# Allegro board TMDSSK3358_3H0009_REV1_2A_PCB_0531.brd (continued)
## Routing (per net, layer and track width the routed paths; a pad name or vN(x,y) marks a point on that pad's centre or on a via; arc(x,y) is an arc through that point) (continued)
AM335X_MMC0_D3: length 82.7
  TOP w0.14: R3.1 99.82,66.93 99.81,66.95 v1(99.06,66.95) ; U1.3 v1(105.02,63.86)
  LY6_SIG2 w0.127: v1(99.06,66.95) 99.52,67.41 99.52,67.99 99.11,68.4 98.51,68.4 97.92,67.82 94.05,67.82 93.68,67.45 93.68,66.46 93.86,66.27 94.62,66.27 94.8,66.08 94.8,65.82 94.62,65.64 93.86,65.64 93.68,65.45 93.68,65.19 93.86,65 94.62,65 94.8,64.81 94.8,64.55 94.62,64.37 93.86,64.37 93.68,64.18 93.68,63.92 93.86,63.73 94.62,63.73 94.8,63.54 94.8,63.28 94.62,63.1 93.86,63.1 93.68,62.91 93.68,62.65 93.86,62.46 94.62,62.46 94.8,62.27 94.8,62.01 94.62,61.83 93.86,61.83 93.68,61.64 93.68,61.38 93.86,61.19 94.62,61.19 94.8,61 94.8,60.74 94.62,60.56 93.86,60.56 93.68,60.37 93.68,59.38 93.97,59.09 96.88,59.09 97.21,58.76 97.21,55.23 96.94,54.97 92.53,54.97 90.53,56.97 79.45,56.97 77.54,55.05 77.54,53.55 75.67,51.68 75.67,50.2 74.44,48.98 74.44,43.11 75.84,41.72 v2(75.92,41.72)
  BOTTOM w0.14: U26.F17 75.92,39.43 v2(75.92,41.72) ; v1(105.02,63.86) 102.65,63.86 101.2,65.3 100.7,65.3 v1(99.06,66.95) J4.2
AM335X_OSC0_IN: length 14.6
  BOTTOM w0.14: U26.V10 65.86,33.41 65.46,33.02 63.68,33.02 63.25,32.58 63.25,31.87 62.72,31.34 62.72,28.14 62.26,27.69 R216.2 C250.2 60.26,27.3 60.26,27.11 60.11,26.96 58.37,26.96 57.68,27.65 Y6.3
AM335X_OSC0_OUT: length 7.6
  BOTTOM w0.14: R213.1 62.85,32.06 62.85,32.67 63.53,33.35 65.39,33.35 65.86,33.82 67.15,33.82 U26.U11
AM335X_OSC1_IN: length 14.1
  BOTTOM w0.14: U26.A6 82.26,30.21 82.45,30.02 86.52,30.02 87.29,30.79 87.83,30.79 88.19,30.44 88.43,30.44 C247.2 89.13,29.84 89.92,29.06 89.92,27.91 91.36,26.47 Y7.4
AM335X_OSC1_OUT: length 7.9
  BOTTOM w0.14: U26.A4 81.79,28.61 82.45,27.95 86.96,27.95 87.22,27.69 R217.1
AM335X_RGMII1_MDIO_CLK: length 72
  TOP w0.14: R25.2 91.46,46.27 v1(92.84,46.27)
  LY3_SIG1 w0.127: v1(51.05,46.84) 52.54,48.32 53.65,48.32 53.73,48.4 54.8,48.4 55.23,48.83 56.02,48.83 56.53,48.32 60.34,48.32 60.84,47.82 66.1,47.82 67.54,46.37 67.54,42.99 67.62,42.92 67.62,42.87 68.13,42.36 68.13,42.22 68.86,41.49 70.51,41.49 70.75,41.74 70.75,42.65 71.13,43.03 v2(71.13,43.54) 70.78,43.88 70.78,46.01 70.97,46.2 70.97,49.96 73.1,52.08 77.94,52.08 78.16,52.3 87.12,52.3 87.56,51.86 87.56,50.74 88.44,49.86 89.24,49.86 v1(92.84,46.27)
  BOTTOM w0.14: v1(51.05,46.84) R147.2 ; U26.M18 71.54,40.6 71.54,41.95 71.55,41.96 71.55,42.08 71.63,42.16 71.63,43.04 v2(71.13,43.54) ; v1(92.84,46.27) 92.84,44.08 93.81,43.1 U23.1
AM335X_RGMII1_MDIO_DATA: length 79.7
  TOP w0.14: R30.1 91.95,43.48 v1(92.04,43.38)
  LY3_SIG1 w0.127: v1(50.27,46.84) 50.78,46.33 51.41,46.33 52.83,47.75 53.8,47.75 53.94,47.89 55.01,47.89 55.44,48.32 55.81,48.32 56.7,47.43 58.87,47.43 59.11,47.67 60.23,47.67 60.61,47.29 62.95,47.29 66.78,43.47 66.78,41.82 67.41,41.19 70.53,41.19 71.12,41.78 71.12,42.37 v2(71.22,42.47) 71.53,42.16 71.53,41.69 71.78,41.44 72.6,41.44 73.27,42.11 73.27,42.85 74,43.59 75.51,43.59 75.54,43.61 75.85,43.61 76.26,44.02 76.68,44.02 79.57,44.02 79.82,43.76 84.2,43.76 85.12,42.84 85.33,42.84 86.19,41.97 86.19,41.23 86.39,41.04 86.39,40.09 87.01,39.47 87.01,38.96 87.59,38.38 87.96,38.38 87.96,38.38 88.41,38.38 89.33,37.47 89.33,36.71 90.86,35.18 93.17,35.18 94.21,34.14 94.63,34.14 95.27,34.78 95.27,41.12 93.01,43.38 v1(92.04,43.38)
  BOTTOM w0.14: U23.48 93.34,41.95 93.49,42.1 93.49,42.3 92.41,43.38 v1(92.04,43.38) ; U26.M17 71.12,39.43 71.12,42.37 v2(71.22,42.47) ; R148.2 50.04,45.49 50.27,45.72 v1(50.27,46.84)
AM335X_RGMII1_RXCLK: length 43.5
  LY3_SIG1 w0.127: v2(72.45,42.48) 72.3,42.62 72.3,47.25 72.13,47.42 72.13,48.47 73.07,49.42 77.11,49.42 77.38,49.14 79.84,49.14 79.98,49.28 86.54,49.28 88.62,47.19 88.62,46.08 94.19,40.52 94.19,36.38 94.76,35.81 94.76,34.99 v1(94.42,34.65)
  BOTTOM w0.14: R208.2 94.42,33.6 v1(94.42,34.65) ; v2(72.45,42.48) 72.45,42.18 72.68,41.95 72.68,40.57 72.34,40.24 U26.L18
AM335X_RGMII1_RXD0: length 67.9
  LY3_SIG1 w0.127: v1(96.17,55.73) 96.17,43.56 98.36,41.38 98.36,34.36 v1(99.82,32.89)
  LY6_SIG2 w0.127: v2(71.14,38.61) 71.14,41.77 71.62,42.25 71.62,42.63 71.19,43.05 71.02,43.05 70.71,43.37 70.71,44.85 72.02,46.16 73.13,46.16 73.94,46.97 73.94,49.23 75.16,50.45 75.16,51.89 77.03,53.76 77.03,55.3 79.34,57.6 90.73,57.6 91.56,58.44 93.46,58.44 v1(96.17,55.73)
  BOTTOM w0.14: v1(99.82,32.89) 99.31,32.39 R204.2 ; U26.M16 v2(71.14,38.61)
AM335X_RGMII1_RXD1: length 39.7
  LY3_SIG1 w0.127: v1(100.69,30.71) 99.81,29.83 99.81,28.55 98.69,27.43 94.99,27.43 93.02,29.4 92.71,29.4 90.26,31.85 89.91,31.85 87.81,33.95 87.34,33.95 86.4,34.89 86.4,35.14 85.59,35.95 85.59,36.13 85.33,36.39 85.32,36.39 84.54,37.16 84.54,37.76 83.85,38.45 80.83,38.45 79.79,37.41 77.15,37.41 76.36,36.62 74.06,36.62 73.27,37.41 72.34,37.41 v2(71.94,37.81)
  BOTTOM w0.14: v1(100.69,30.71) 100.33,31.07 R203.2 ; U26.L15 v2(71.94,37.81)
AM335X_RGMII1_RXD2: length 43.9
  TOP w0.14: v1(100.85,31.44) 99.91,32.39 R69.2
  LY3_SIG1 w0.127: v2(71.94,38.61) 71.54,38.22 71.54,37.65 72.58,36.62 73.26,36.62 74.06,35.82 76.44,35.82 77.24,36.62 79.72,36.62 81.32,38.23 83.08,38.23 84.04,37.27 84.04,36.42 85.06,35.39 85.4,35.39 85.89,34.91 85.89,34.68 87.13,33.44 87.39,33.44 87.87,32.96 87.89,32.96 88.15,32.7 88.15,32.68 89.52,31.31 89.85,31.31 92.64,28.51 93.15,28.51 94.74,26.92 98.9,26.92 99.47,27.48 99.51,27.48 100.32,28.29 100.32,29.57 101.23,30.49 101.23,31.06 v1(100.85,31.44)
  BOTTOM w0.14: U26.L16 v2(71.94,38.61)
AM335X_RGMII1_RXD3: length 57.4
  TOP w0.14: R71.2 103.66,32.39 v1(103.69,32.41)
  LY3_SIG1 w0.127: v2(71.95,41.83) 71.76,42.02 71.76,47.02 71.62,47.16 71.62,48.79 73.68,50.84 77.69,50.84 78.32,50.22 87.13,50.22 87.71,49.63 87.71,49.01 90.42,46.31 91.35,46.31 95.12,42.55 96.39,42.55 97.78,41.15 97.78,33.03 98.43,32.38 100.03,32.38 100.27,32.63 103.47,32.63 v1(103.69,32.41)
  BOTTOM w0.14: v2(71.95,41.83) 72.39,41.39 72.39,40.63 71.95,40.19 71.95,39.41 U26.L17
AM335X_RGMII1_RXDV: length 33.4
  LY3_SIG1 w0.127: v1(96.22,32.89) 95.58,33.53 94.1,33.53 92.96,34.67 90.65,34.67 88.82,36.5 88.82,37.18 88.13,37.87 87.38,37.87 86.48,38.77 86.48,39.29 86.08,39.68 85.86,39.9 85.86,40.75 84.13,42.48 81.19,42.48 80.49,43.18 79.51,43.18 79.18,43.51 76.47,43.51 76.06,43.1 75.75,43.1 75.51,42.86 75.51,42.82 75.18,42.5 74.02,42.5 v2(73.83,42.7)
  BOTTOM w0.14: R206.2 96.44,32.85 96.27,32.85 v1(96.22,32.89) ; v2(73.83,42.7) 73.55,42.42 73.55,39.41 U26.J17
AM335X_RGMII1_TXCLK: length 32.8
  LY3_SIG1 w0.127: v1(73.39,48.35) 73.92,48.88 76.92,48.88 77.28,48.52 79.94,48.52 80.2,48.26 83.28,48.26 84.37,47.17 85.67,47.17 89.98,42.86 89.98,42.28 90.54,41.72 91.43,41.72 92.92,40.23 v1(92.92,35.71)
  BOTTOM w0.14: U23.35 94.21,36.22 94.11,36.11 94.06,36.11 94,36.05 93.99,36.05 93.98,36.04 93.25,36.04 v1(92.92,35.71) ; R134.1 73.84,46.24 74.25,46.64 74.25,47.5 v1(73.39,48.35)
AM335X_RGMII1_TXD0: length 28.9
  LY3_SIG1 w0.127: v1(73.41,47.3) 75.1,45.62 75.1,45.47 75.41,45.15 76.37,45.15 76.7,44.82 80.28,44.82 80.83,44.27 84.41,44.27 85.33,43.35 85.54,43.35 86.7,42.18 86.7,41.44 86.93,41.21 86.93,40.28 87.29,39.91 88.05,39.91 90.48,37.47 90.48,37.25 90.8,36.92 90.8,35.98 91.1,35.69 92.1,35.69 v1(92.18,35.76)
  BOTTOM w0.14: R135.1 73.41,46.81 v1(73.41,47.3) ; v1(92.18,35.76) 92.66,36.25 92.66,36.57 92.77,36.68 U23.36
AM335X_RGMII1_TXD1: length 21.9
  LY3_SIG1 w0.127: v1(79.84,46.95) 80.34,46.45 80.95,46.45 81.24,46.15 84.71,46.15 88.51,42.35 88.52,42.35 88.96,41.91 88.96,41.73 91.5,39.19 91.5,37.67 91.83,37.33 91.83,36.69 v1(92.08,36.45)
  BOTTOM w0.14: v1(92.08,36.45) 91.83,36.69 91.83,37.11 92.27,37.55 U23.37 ; R130.1 79.01,46.95 v1(79.84,46.95)
AM335X_RGMII1_TXD2: length 27.8
  LY3_SIG1 w0.127: v1(72.76,47.5) 72.76,47.52 73.07,47.83 75.62,47.83 76.45,47 79.11,47 79.51,47.4 80.72,47.4 81.45,46.66 84.92,46.66 88.72,42.86 88.73,42.86 89.47,42.12 89.47,42.07 91.09,40.45 91.75,40.45 92.01,40.19 92.01,37.96 v1(92.01,37.95)
  BOTTOM w0.14: v1(72.76,47.5) 72.4,47.15 72.4,46.82 R136.1 ; v1(92.01,37.95) U23.38
AM335X_RGMII1_TXD3: length 25.9
  LY3_SIG1 w0.127: v1(75.6,45.68) 75.68,45.76 80.79,45.76 81.77,44.78 84.62,44.78 85.54,43.86 85.75,43.86 87.21,42.39 87.21,41.65 90.99,37.87 90.99,37.46 91.31,37.13 v1(91.31,36.2)
  BOTTOM w0.14: R133.1 75.05,46.23 v1(75.6,45.68) ; U23.39 92.28,38.35 92.21,38.42 92.13,38.42 92.13,38.43 91.52,38.43 91,37.91 91,36.76 91.31,36.45 v1(91.31,36.2)
AM335X_RGMII1_TXEN: length 26.5
  LY3_SIG1 w0.127: v1(94.25,35.6) 93.43,36.42 93.43,40.44 91.64,42.23 90.75,42.23 90.49,42.49 90.49,43.07 84.79,48.77 v1(80.67,48.77)
  BOTTOM w0.14: v1(80.67,48.77) 80.4,48.49 80.4,46.67 79.95,46.23 R129.1 ; U23.34 94.61,35.95 94.25,35.59 94.25,35.6 v1(94.25,35.6)
AM335X_RGMII2_RXCLK: length 22.7
  LY3_SIG1 w0.127: v2(67.94,37.81) 66.92,36.79 66.92,35.17 64.26,32.52 64.26,32.34 63.9,31.97 60.51,31.97 60.09,32.4 57.99,32.4 57.58,31.98 57.58,31.59 57.08,31.09 52.98,31.09 52.19,31.88 v1(51.31,31.88)
  BOTTOM w0.14: v1(51.31,31.88) 51.31,31.88 R200.2 ; U26.T15 v2(67.94,37.81)
AM335X_RGMII2_RXD0: length 17.1
  LY3_SIG1 w0.127: v1(56.11,31.85) 56.11,32.2 57.5,33.6 62.93,33.6 64.36,35.03 65,35.03 65.23,35.26 65.23,35.58 64.81,36 64.81,38.25 v2(65.39,38.82)
  BOTTOM w0.14: v1(56.11,31.85) 56.11,32.3 R195.2 ; U26.V17 66.51,39.01 66.5,39.01 66.17,39.01 66.17,39.01 65.57,39.01 v2(65.39,38.82)
AM335X_RGMII2_RXD1: length 17.8
  LY3_SIG1 w0.127: v1(58.42,31.84) 58.42,31.52 58.73,31.21 63.56,31.21 63.76,31.01 64.29,31.01 64.52,31.24 64.52,32.29 67.27,35.04 67.27,36.14 68.33,37.21 68.33,38.22 v2(67.94,38.61)
  BOTTOM w0.14: v1(58.42,31.84) 58.04,31.84 57.8,32.08 57.8,32.3 R194.2 ; U26.T16 v2(67.94,38.61)
AM335X_RGMII2_RXD2: length 16.7
  TOP w0.14: v1(56.81,31.9) 56.81,32.18 R65.2
  LY3_SIG1 w0.127: v2(67.14,38.61) 66.54,38.01 66.54,35.42 64.26,33.15 63.96,33.15 63.5,32.69 61.38,32.69 60.91,33.16 57.68,33.16 56.81,32.3 v1(56.81,31.9)
  BOTTOM w0.14: U26.U16 v2(67.14,38.61)
AM335X_RGMII2_RXD3: length 10.5
  TOP w0.14: R67.2 61.18,33.11 v1(61.72,33.11)
  LY3_SIG1 w0.127: v1(61.72,33.11) 63.35,33.11 63.86,33.63 64.42,33.63 65.72,34.92 65.72,37.99 v2(66.34,38.61)
  BOTTOM w0.14: U26.V16 v2(66.34,38.61)
AM335X_RGMII2_RXDV: length 15.5
  LY3_SIG1 w0.127: v2(63.75,36.61) 63.41,36.27 63.41,35.66 62.37,34.62 62.12,34.62 61.54,34.03 56.9,34.03 v1(54.74,31.88)
  BOTTOM w0.14: v1(54.74,31.88) 54.45,32.17 54.41,32.2 R197.2 ; v2(63.75,36.61) 64.43,36.61 64.73,36.32 66.41,36.32 66.49,36.4 66.53,36.4 U26.V14
AM335X_RGMII2_TXCLK: length 22.9
  LY3_SIG1 w0.127: v1(52.83,34.92) 51.01,34.92 50.02,35.92 50.02,37.85 50.65,38.48 53.53,38.48 53.97,38.04 57.24,38.04 57.46,38.25 60.05,38.25 60.29,38.02 61,38.02 v1(62.65,39.67)
  BOTTOM w0.14: v1(52.83,34.92) 53.27,35.36 53.27,35.57 53.83,36.13 U24.35 ; v1(62.65,39.67) 62,40.32 62,40.54 R168.1
AM335X_RGMII2_TXD0: length 17.8
  LY3_SIG1 w0.127: v1(62.69,38.92) 62.51,38.92 61.18,37.59 60.11,37.59 59.87,37.82 57.64,37.82 57.42,37.6 53.66,37.6 53.56,37.7 51.73,37.7 51.01,36.99 51.01,36.36 51.46,35.92 v1(52.72,35.92)
  BOTTOM w0.14: R174.1 62.1,38.92 v1(62.69,38.92) ; U24.36 53.43,36.2 53.15,35.92 v1(52.72,35.92)
AM335X_RGMII2_TXD1: length 15.6
  TOP w0.14: R51.1 64.4,38.46 64.24,38.61 63.88,38.61 v2(63.63,38.35)
  LY3_SIG1 w0.127: v1(52.09,36.83) 52.79,36.83 52.87,36.74 58.27,36.74 59.19,35.83 61.44,35.83 62.91,37.29 62.91,37.64 v2(63.63,38.35)
  BOTTOM w0.14: U24.37 52.55,37.29 v1(52.09,36.83)
AM335X_RGMII2_TXD2: length 15.1
  LY3_SIG1 w0.127: v1(62.36,37.34) 61.74,37.34 60.66,36.26 59.37,36.26 58.45,37.17 53.26,37.17 53.16,37.27 51.9,37.27 51.46,36.83 v1(51.46,36.54)
  BOTTOM w0.14: R180.1 v1(62.36,37.34) ; U24.38 51.98,37.95 51.46,37.43 v1(51.46,36.54)
AM335X_RGMII2_TXD3: length 19.1
  LY3_SIG1 w0.127: v1(61.8,35.36) 59.04,35.36 58.14,36.26 54.02,36.26 53.23,35.47 51.29,35.47 50.56,36.21 v1(50.56,37.47)
  BOTTOM w0.14: R192.1 61.8,33.93 v1(61.8,35.36) ; U24.39 51.83,38.35 50.94,37.47 v1(50.56,37.47)
AM335X_RGMII2_TXEN: length 14.7
  TOP w0.14: v2(63.63,37.47) 63.91,37.19 64.07,37.19 R56.1
  LY3_SIG1 w0.127: v1(53.91,35.06) 54.21,35.37 56.41,35.37 56.43,35.39 58.4,35.39 58.99,34.8 60.62,34.8 60.73,34.91 62.32,34.91 62.81,35.4 62.81,36.65 v2(63.63,37.47)
  BOTTOM w0.14: U24.34 54.23,36.01 53.91,35.69 v1(53.91,35.06)
AM335X_SPI0_CS0: length 50.2
  TOP w0.14: J11.2 100.72,15.13 v1(100.72,16.58)
  BOTTOM w0.14: U26.A16 80.36,38.23 81.92,38.23 82.39,38.7 83.53,38.7 84.4,37.83 85.54,37.83 R179.1 86.44,36.93 88.12,36.93 91.65,33.4 91.65,32.16 93.14,30.68 94.53,30.68 94.93,31.08 97.93,31.08 99.99,29.02 99.99,28.24 101.21,27.02 104.17,27.02 105.73,25.46 105.73,25.09 104.82,24.18 101.21,24.18 100.34,23.31 100.34,16.96 v1(100.72,16.58)
AM335X_SPI0_CS1: length 40.6
  TOP w0.14: v2(79.14,37.81) 78.74,38.21 78.74,38.78 78.17,39.35 78.17,40.39 78.77,40.98 78.77,41.09 80.15,42.48 84.33,42.48 85.47,43.61 86.96,43.61 88.78,45.43 88.78,45.51 90.9,47.63 95.95,47.63 96.36,47.22 v1(98.36,47.22) ; v1(98.81,57.4) R11.1 98.81,58.3 U2.3
  BOTTOM w0.14: v1(98.36,47.22) 98.04,47.53 98.04,49.92 96.66,51.3 96.66,53.23 98.04,54.62 98.04,55.37 98.8,56.13 J4.10 98.81,56.26 v1(98.81,57.4) ; U26.C15 78.74,37.41 v2(79.14,37.81)
AM335X_SPI0_D0: length 71.4
  BOTTOM w0.14: U26.B17 79.99,39.46 80.48,39.46 81.03,40.01 81.03,40.05 81.8,40.81 83.07,40.81 83.87,40.02 87.92,40.02 88.32,39.62 88.32,38.61 88.25,38.55 88.25,37.32 90.29,35.29 91.36,35.29 92.85,33.8 92.85,31.48 93.29,31.05 94.37,31.05 94.78,31.45 98.08,31.45 100.4,29.13 100.4,28.39 101.4,27.39 104.33,27.39 106.1,25.61 106.1,24.93 104.98,23.81 101.37,23.81 100.72,23.16 100.72,18.24 101.29,17.67 101.29,16.4 100.9,16.01 99,16.01 97.65,14.66 97.2,14.66 96.83,14.3 94.61,14.3 94.22,14.68 93.84,14.68 93.03,15.49 93.03,16.07 92.1,17 92.1,17.46 92.1,18.27 91.76,18.61 91.28,18.61 90.8,18.13 90.44,18.13 90.16,17.85 90.16,16.99 90.11,16.95 90.11,15.47 89.77,15.12 89.77,14.33 J11.6
AM335X_SPI0_D1: length 44.4
  LY6_SIG2 w0.127: v1(84.33,38.61) 84.33,38.58 84.21,38.47 84.21,37.03 84.78,36.46 85.26,36.46 86.29,35.43 86.29,34.87 91.05,30.11 91.05,28.87 92.8,27.11 93.6,27.11 96.8,23.92 96.8,22.77 100.59,18.98 100.59,18.7 v1(101.74,17.55)
  BOTTOM w0.14: v1(101.74,17.55) 101.74,16.33 101.05,15.64 99.15,15.64 97.8,14.3 97.35,14.3 J11.3 ; R177.1 85.63,38.2 84.73,38.2 v1(84.33,38.61) 84.33,38.59 83.8,39.12 82.32,39.12 81.81,38.61 79.93,38.61 U26.B16
AM335X_SPI0_SCLK: length 42.9
  TOP w0.14: J11.5 92.21,14.23 97.64,14.23 98.08,14.23 99.89,16.05 99.89,16.73 101.49,18.33 101.49,21.27 101.49,22.87 101.49,23.18 101.49,27.65 100.65,28.48 100.65,29.87 98.64,31.87 97.83,31.87 97.19,32.51 97.19,33.4 92.19,38.4 90.46,38.4 90.15,38.71 89,38.71 88.29,39.43 87.68,39.43 v1(87.66,39.45)
  BOTTOM w0.14: R171.2 87.61,39.5 v1(87.66,39.45)
AM335X_UART0_CTSN: length 60.3
  LY6_SIG2 w0.127: v1(40.55,29.67) 40.55,31.15 41.89,32.5 43.6,32.5 44.13,31.97 47.02,31.97 47.96,31.03 56.52,31.03 57.63,29.91 63.64,29.91 64.27,30.54 64.27,30.56 64.92,31.21 65.28,31.21 65.6,31.53 65.6,32.44 65.6,32.45 65.6,32.78 65.83,33.01 66.52,33.01 67.7,31.82 68.9,31.82 69.13,32.05 69.13,32.47 70.28,33.62 70.28,36.18 70.71,36.62 72.9,36.62 73.13,36.85 73.13,37.99 72.9,38.22 72.58,38.22 72.34,38.45 72.34,39.5 74.03,41.19 75.95,41.19 76.32,41.56 76.32,42.2 v2(76.79,42.67)
  BOTTOM w0.102: v2(76.79,42.67) 77.14,42.32 U26.E18
  BOTTOM w0.14: U28.40 36.86,28.58 37.93,29.64 40.52,29.64 v1(40.55,29.67)
AM335X_UART0_RTSN: length 199
  TOP w0.14: v1(114.57,29.03) 109.61,33.98 v1(104.47,33.98)
  LY3_SIG1 w0.127: v2(76.75,41.72) 77.67,40.79 80.62,40.79 81.45,39.96 83.19,39.96 83.76,39.38 84.65,39.38 85.26,38.78 85.26,38.32 86.76,36.81 86.76,35.96 87.24,35.49 87.24,35.24 87.69,34.79 88.74,34.79 90.3,33.22 90.85,33.22 95.24,28.83 96.09,28.83 97.23,29.97 98.37,29.97 100.51,32.12 102.99,32.12 103.21,31.9 103.9,31.9 104.26,32.27 104.26,33.07 104.27,33.08 104.27,33.78 104.48,33.98 v1(104.47,33.98) ; v1(33.48,28.78) 29.55,24.84 29.55,23.44 28.39,22.29 28.39,7.7 33.02,3.07 40.78,3.07 40.83,3.12 42.63,3.12 43.97,1.79 55.26,1.79 55.78,2.31 57.96,2.31 59.4,0.88 97.51,0.88 98.03,1.4 110.53,1.4 117.54,8.4 117.54,24.24 114.06,27.72 114.06,28.52 v1(114.57,29.03)
  BOTTOM w0.14: U28.41 33.78,29.08 v1(33.48,28.78) ; U26.E17 76.75,39.41 v2(76.75,41.72) 76.75,42.15 76.35,42.55 76.35,43.42 77.27,44.35 R131.1
AM335X_UART0_RXD: length 72.3
  LY3_SIG1 w0.127: v1(31.13,42.49) 31.13,42.64 32.5,44.01 36.89,44.01 37.15,44.27 37.15,44.51 37.53,44.89 48.34,44.89 50.68,42.56 57.56,42.56 57.99,42.99 59.03,42.99 59.19,42.83 60.28,42.83 61,43.55 61.85,43.55 63.27,42.13 63.72,42.13 66.03,39.81 66.34,39.81 69.82,39.81 70.28,39.35 72.9,39.35 73.14,39.1 73.14,38.45 73.38,38.22 73.69,38.22 73.95,37.96 73.95,37.65 74.18,37.42 76.54,37.42 76.94,37.81 v2(77.54,37.81)
  LY6_SIG2 w0.127: v1(37.19,28.08) 37.19,29.03 34.92,31.3 34.92,35.01 34.3,35.63 34.3,39.44 32.86,40.89 32.73,40.89 v1(31.13,42.49)
  BOTTOM w0.14: U26.E15 v2(77.54,37.81) ; v1(37.19,28.08) 36.69,27.58 U28.38
AM335X_UART0_TXD: length 151
  LY3_SIG1 w0.127: v1(34.88,3.56) 34.27,4.17 33.02,4.17 32.77,4.42 32.77,5.46 29.61,8.62 29.61,21.59 31.61,23.58 31.61,25.4 32.77,26.56 32.91,26.56 33.41,27.06 33.41,27.45 33.11,27.76 v1(33.1,27.76)
  LY6_SIG2 w0.127: v1(34.88,3.56) 42.42,3.56 44.03,5.16 54.74,5.16 56.96,2.95 60.73,2.95 62.47,1.21 83.33,1.21 84.34,2.21 84.5,2.37 87.28,2.37 89.23,4.33 98.87,4.33 100.56,6.01 100.56,11.78 100.15,12.19 100.15,13.71 99.4,14.45 97.87,14.45 94.3,18.02 94.3,20.31 92.79,21.82 92.79,24.63 88.27,29.15 86.38,29.15 84.75,30.77 84.75,31.64 83.56,32.84 82.93,32.84 82.5,33.27 82.22,33.27 81.85,33.64 81.85,34.79 82.26,35.2 82.63,35.2 83.44,36.01 83.44,37.76 82.36,38.84 81.15,38.84 80.98,39.01 77.93,39.01 v2(77.54,38.61)
  BOTTOM w0.14: v1(33.1,27.76) 33.42,28.08 U28.39 ; U26.E16 v2(77.54,38.61)
AM335X_UART1_CTSN: length 82.2
  TOP w0.14: v1(95.81,29.27) 95.81,28.9 98.24,26.47 98.24,25.45 98.82,24.88 98.82,22.24 98.07,21.5 97.36,21.5 97.08,21.78 95.69,21.78 95.61,21.8 95.59,21.8 94.35,21.8 93.82,21.27 93.42,20.87 88.89,20.87 87.67,19.65 81.65,19.65 80.55,18.56 63.94,18.56 63.89,18.61 63.52,18.61 61.07,16.16 58.61,16.16 57.53,17.25 U11.7
  LY3_SIG1 w0.127: v1(95.81,29.27) 95.81,30.96 93.3,33.48 91.59,33.48 90.91,34.16 90.44,34.16 88.31,36.29 88.31,36.6 88,36.92 87.61,36.92 85.94,38.58 85.94,39.02 83.64,41.33 81.63,41.33 80.32,42.63 77.57,42.63 v2(77.52,42.68)
  BOTTOM w0.14: U26.D18 77.94,42.27 v2(77.52,42.68)
AM335X_UART1_RTSN: length 82.9
  TOP w0.14: v1(95.21,29.75) 95.98,29.75 98.61,27.12 98.61,26.06 98.61,25.61 99.19,25.03 99.19,22.09 98.23,21.13 97.2,21.13 96.92,21.41 95.59,21.41 95.58,21.43 95.54,21.43 94.5,21.43 93.97,20.9 93.57,20.5 92.34,20.5 91.07,19.23 88.86,19.23 88.55,18.92 81.95,18.92 80.75,17.72 80.71,17.71 64.41,17.71 62.13,15.42 58.07,15.42 57.55,15.95 U11.5
  LY3_SIG1 w0.127: v2(77.52,41.72) 78.56,41.72 79.09,41.18 80.99,41.18 81.22,40.95 82.72,40.95 83.81,39.86 84.64,39.86 85.59,38.91 85.59,38.47 87.12,36.94 87.12,36.07 87.57,35.63 87.57,35.38 87.83,35.12 89.02,35.12 90.38,33.76 90.78,33.76 91.39,33.15 93.16,33.15 95.21,31.11 v1(95.21,29.75)
  BOTTOM w0.14: v2(77.52,41.72) 77.52,39.43 U26.D17
AM335X_UART1_RXD: length 59
  TOP w0.14: U11.6 57.53,16.6 58.33,15.79 61.97,15.79 63.31,17.13 64.26,18.08 80.54,18.08 80.6,18.09 81.8,19.29 87.96,19.29 v1(88.73,20.05)
  LY6_SIG2 w0.127: v1(88.73,20.05) 88.73,23.28 87.31,24.7 87.31,25.01 87.05,25.27 86.09,25.27 79.53,31.82 79.53,34.78 79.29,35.02 78.98,35.02 78.75,35.25 78.75,36.37 78.5,36.61 78.19,36.61 77.95,36.85 77.95,38.22 v2(78.34,38.61)
  BOTTOM w0.14: U26.D16 v2(78.34,38.61)
AM335X_UART1_TXD: length 63.7
  TOP w0.14: U11.4 57.58,15.3 58.22,14.66 60.72,14.66 61.12,15.06 62.28,15.06 64.56,17.34 80.88,17.34 80.9,17.35 82.1,18.55 88.97,18.55 88.97,18.55 89.23,18.81 89.83,18.81 90.61,18.03 v1(90.61,17.64)
  LY6_SIG2 w0.127: v2(78.34,37.81) 78.75,37.41 78.75,36.85 78.99,36.61 79.3,36.61 79.99,35.92 79.99,32.44 86.41,26.03 88.01,26.03 89.74,24.29 89.74,19.02 90.61,18.16 90.61,17.65 v1(90.61,17.64)
  BOTTOM w0.14: U26.D15 v2(78.34,37.81)
AM335X_USB0_CE: length 18.1
  LY6_SIG2 w0.127: v1(72.57,48.29) 71.83,47.55 71.83,46.98 69.86,45.01 69.86,41.17 70.74,40.29 70.74,38.21 v2(71.14,37.81)
  BOTTOM w0.14: TP3.1 74.23,51.29 74.23,49.19 73.92,48.88 73.16,48.88 v1(72.57,48.29) ; U26.M15 v2(71.14,37.81)
AM335X_USB1_CE: length 8.6
  BOTTOM w0.14: U26.P18 69.94,45.82 71.3,47.18 TP6.1
AM335X_USB1_DRVVBUS: length 70.2
  TOP w0.14: v1(14.81,47.07) 15.63,46.25 16.65,46.25 17.61,45.29 19.96,45.29 20.35,44.91 31.2,44.91 v1(31.71,44.4)
  LY3_SIG1 w0.127: v1(31.71,44.4) 32.24,44.93 36.25,44.93 36.54,45.22 48.48,45.22 50.82,42.89 57.18,42.89 58.05,43.75 60.73,43.75 60.94,43.96 61.91,43.96 63.32,42.55 63.62,42.55 66.13,40.04 66.43,40.04 66.62,40.04 67,40.04 70.02,40.04 70.44,39.63 73.1,39.63 74.52,38.21 75.55,38.21 v2(75.94,37.81)
  BOTTOM w0.14: v1(14.81,47.07) R127.1 U18.4 ; U26.F15 v2(75.94,37.81)
AM335X_USB1_OC: length 185.9
  LY3_SIG1 w0.127: v1(13.29,56.59) 17.67,52.21 17.67,46.11 17.67,46.11 17.67,43.69 20.01,41.35 20.01,40.74 26.56,34.18 26.56,24.19 27.71,23.05 27.71,16.42 26.16,14.88 26.16,14.1 27.71,12.55 27.71,7.21 33.29,1.63 33.33,1.63 33.86,1.09 40.44,1.09 v1(40.98,1.63)
  LY6_SIG2 w0.127: v2(83.57,35.41) 84.48,35.41 84.77,35.11 84.77,34.77 85.03,34.51 85.38,34.51 86.91,32.98 86.91,32.21 87.62,31.5 87.62,31.09 88.2,30.51 88.52,30.51 93.43,25.6 93.62,25.6 96.21,23.02 96.21,22.64 97.63,21.22 97.63,18.63 97.93,18.33 97.93,18.31 100.16,16.07 101.49,16.07 104.15,13.41 104.15,8.59 103.2,7.64 103.2,5.22 101.98,4 90.95,4 88.28,1.33 84.71,1.33 84.25,0.88 58.67,0.88 57.3,2.25 55.86,2.25 55.24,1.63 v1(40.98,1.63)
  BOTTOM w0.14: U26.B12 79.93,35.41 80.91,35.41 81.05,35.27 81.98,35.27 81.98,35.27 83.43,35.27 v2(83.57,35.41) ; v1(13.29,56.59) R102.1 U18.5
AM335X_USB1_VBUS: length 9.7
  BOTTOM w0.14: U26.T18 68.34,42.66 67.88,43.13 C214.1 67.81,44.9 D6.1 66.67,44.9 66.41,45.15 66.41,46.65 67.16,47.4 R126.2
AM335X_XDMA_EVENT_INTR0: length 124.2
  LY3_SIG1 w0.127: v1(105.42,3.75) 104.91,3.25 91.35,3.25 90.46,2.35 85.89,2.35 85.48,2.77 83.26,2.77 82.78,2.29 77.77,2.29 77.2,1.71 59.75,1.71 57.59,3.87 56.41,3.87 53.28,7.01 53.28,10.71 51.04,12.94 51.04,13.31 49.05,15.3 46.31,15.3 46.1,15.09 44.95,15.09 44.6,15.45 38.03,15.45 v1(36.87,16.6)
  LY6_SIG2 w0.127: v1(105.42,3.75) 104.6,4.58 104.6,8.01 105.22,8.63 105.22,17.67 104.66,18.23 104.66,20.87 103.65,21.88 100.6,21.88 93.97,28.51 92.48,28.51 91.55,29.44 91.55,30.32 89.32,32.55 89.32,34.22 88.87,34.67 88.27,34.67 87.57,35.38 87.57,36.23 v1(87.81,36.47)
  BOTTOM w0.14: U31.37 37.08,15.93 36.87,16.15 v1(36.87,16.6) ; R186.1 87.73,36.32 87.81,36.41 v1(87.81,36.47)
AM335X_XDMA_EVENT_INTR1: length 101.9
  TOP w0.14: R52.1 82.57,37.59 v2(82.81,37.83)
  LY3_SIG1 w0.127: v1(54.99,21.84) 54.99,21.69 56.23,20.45 61.34,20.45 61.85,19.94 61.85,12.43 61.3,11.88 v1(61.3,11.76)
  LY6_SIG2 w0.127: v1(61.3,11.76) 61.3,9.7 61.66,9.34 61.66,6.87 65.09,3.44 83.23,3.44 85.06,5.27 87.01,5.27 88.92,7.18 91.95,7.18 94.26,9.48 95.14,9.48 96.03,10.37 96.03,11.83 95.25,12.61 95.25,14.1 95.52,14.37 95.52,15.31 93.19,17.64 93.19,19.51 91.5,21.2 91.5,24.44 88.57,27.37 86.97,27.37 83.8,30.54 83.8,31.4 83.06,32.14 82.85,32.14 82.34,32.64 82.03,32.64 81.08,33.58 81.08,35.46 82.22,36.6 82.98,36.6 83.21,36.83 83.21,37.43 v2(82.81,37.83)
  BOTTOM w0.14: U29.7 55.57,23.84 54.99,23.26 v1(54.99,21.84)
AM335X_XLEFT: length 95.9
  TOP w0.14: J1.39 50.31,31.34 50.72,30.94 50.72,29.65 52.03,28.35 52.03,24.87 51.52,24.36 51.52,20.83 v1(51.06,20.37)
  LY3_SIG1 w0.127: v1(51.06,20.37) 53.69,20.37 55.17,18.89 55.17,18.75 57.49,16.43 57.49,12.4 58.4,11.49 58.79,11.49 64.48,5.8 75.93,5.8 76.26,6.13 80.9,6.13 84.36,9.59 92.21,9.59 92.85,10.23 92.85,11.63 92.58,11.9 92.58,14.45 93.03,14.89 93.03,19.95 91.07,21.91 91.07,23.51 88.23,26.35 86.89,26.35 85.43,27.81 85.43,27.94 82.51,30.86 v2(82.23,30.86)
  BOTTOM w0.14: v2(82.23,30.86) 81.64,30.86 81.39,30.61 79.93,30.61 U26.B6
AM335X_XRIGHT: length 40.1
  TOP w0.14: v1(48.27,31.7) 48.9,31.7 49.31,32.11 J1.37
  LY3_SIG1 w0.127: v1(48.27,31.7) 48.27,30.74 49.6,29.4 51.09,29.4 51.42,29.07 51.42,29.07 52.89,27.6 55.92,27.6 56.2,27.88 60.88,27.88 61.85,28.84 64.45,28.84 64.6,28.99 65.3,28.99 65.33,28.97 65.83,28.97 66.68,29.82 66.68,30.77 66.99,31.07 67.72,31.07 67.78,31.02 68.9,31.02 69.13,31.25 69.13,31.56 69.38,31.81 76.9,31.81 77.13,31.58 77.13,31.26 78.18,30.22 78.75,30.22 v2(79.14,30.61)
  BOTTOM w0.14: U26.C7 78.74,31.01 v2(79.14,30.61)
AM335X_YDOWN: length 102.3
  TOP w0.14: v1(49.78,20.52) 50.98,21.72 50.98,24.56 51.56,25.13 51.56,28.23 50.32,29.46 50.32,30.63 49.81,31.14 J1.38
  LY3_SIG1 w0.127: v2(83.21,31.43) 83.21,31.23 86.19,28.25 86.19,28.13 87.21,27.11 88.54,27.11 91.83,23.83 91.83,22.23 94.3,19.76 94.3,16.96 95.52,15.74 95.52,14.85 95.25,14.59 95.25,12.34 94.76,11.85 94.76,9.98 93.54,8.76 84.8,8.76 81.22,5.18 76.43,5.18 75.89,4.64 64.35,4.64 61.84,7.16 61.2,7.16 58.91,9.45 58.91,9.66 58.45,10.13 58.36,10.13 56.73,11.75 56.73,14.71 54.39,17.04 54.39,17.06 53.41,18.04 52.96,18.04 52.37,17.45 51.52,17.45 49.78,19.19 v1(49.78,20.52)
  BOTTOM w0.14: v2(83.21,31.43) 81.6,31.43 81.19,31.01 U26.A7
AM335X_YUP: length 100.6
  TOP w0.14: J1.40 50.81,31.55 51.11,31.25 51.11,29.87 52.51,28.47 52.51,21.05 v1(51.04,19.59)
  LY3_SIG1 w0.127: v1(51.04,19.59) 53.94,19.59 54.78,18.75 54.78,17.2 57.11,14.86 57.11,11.91 58.52,10.51 58.6,10.51 59.39,9.72 59.39,9.5 61.36,7.54 61.99,7.54 64.51,5.02 75.73,5.02 76.46,5.75 81.06,5.75 84.51,9.21 93.35,9.21 94.37,10.23 94.37,12.09 94.81,12.52 94.81,13.74 93.56,14.98 93.56,19.96 91.45,22.07 91.45,23.67 88.38,26.73 87.05,26.73 85.81,27.97 85.81,28.1 82.65,31.26 82.65,31.46 v2(82.23,31.88)
  BOTTOM w0.14: v2(82.23,31.88) 81.41,31.88 80.93,31.39 79.92,31.39 U26.B7
AUD_RESETN: length 1.7
  TOP w0.14: R87.1 35.43,14.15 v1(35.43,13.46)
  BOTTOM w0.14: U31.33 v1(35.43,13.46)
BKLT_L: length 0.8
  TOP w0.381: U7.1 26.67,41.68 v1(26.63,41.73)
BKLT_SW: length 0.6
  TOP w0.381: U7.10 v1(29.62,41.56)
CAP_TOUCH_INT: length 25.6
  TOP w0.14: v1(55.62,30.18) 55.62,30.06 55.62,28.97 55.56,28.91 55.56,25.31 55.53,25.28 54.59,24.35 54.59,23.29 55.16,22.73 R80.2
  LY3_SIG1 w0.127: v1(55.62,30.18) 55.8,30.35 61.25,30.35 61.38,30.48 63.18,30.48 63.37,30.29 64.2,30.29 64.52,30.61 64.52,30.86 65.45,31.79 65.45,32.71 67.54,34.8 67.54,35.82 v2(67.94,36.21)
  BOTTOM w0.14: U26.T13 v2(67.94,36.21)
CAP_VBB_MPU: length 16.3
  LY3_SIG1 w0.381: v2(79.14,33.81) 81.23,31.73 81.23,30.74 83.82,28.16 83.83,28.16 86.52,25.46 87.13,25.46 87.13,25.46 87.5,25.09 87.5,23.98 v1(86.87,23.34)
  BOTTOM w0.305: v2(79.14,33.81) 78.74,33.41 U26.C10
  BOTTOM w0.508: v1(86.87,23.34) 86.64,23.34 86.29,23.69 C256.1
CAP_VDD_SRAM_CORE: length 5.2
  TOP w0.381: v2(78.34,33.01) 79.17,33.01 79.69,33.53 79.69,35.69 C83.1
  BOTTOM w0.305: v2(78.34,33.01) 77.94,32.62 U26.D9
CAP_VDD_SRAM_MPU: length 14.5
  LY3_SIG1 w0.381: v2(78.34,33.81) 80.52,31.63 80.52,30.69 83.43,27.78 83.43,27.66 86.25,24.84 86.25,24.83 86.26,24.82 v1(86.87,24.82)
  BOTTOM w0.305: U26.D11 v2(78.34,33.81)
  BOTTOM w0.381: v1(86.87,24.82) 86.49,24.82 86.29,25.02 C254.1
CBB0: length 3.2
  TOP w0.14: RP3.9 41.98,36.32 41.31,35.65 J1.21
CBB1: length 3.3
  TOP w0.14: J1.22 41.81,35.51 42.57,36.27 RP3.10
CBB2: length 3.3
  TOP w0.14: J1.23 42.31,35.4 43.06,36.16 RP3.11
CBB3: length 3.3
  TOP w0.14: RP3.12 43.57,36.07 42.81,35.32 J1.24
CBB4: length 3.3
  TOP w0.14: J1.25 43.31,35.23 44.06,35.99 RP3.13
CBB5: length 3.3
  TOP w0.14: J1.26 43.81,35.07 44.57,35.83 RP3.14
CBB6: length 3.3
  TOP w0.14: J1.27 44.31,34.98 45.06,35.74 RP3.15
CBB7: length 3.3
  TOP w0.14: J1.28 44.81,34.85 45.46,35.5 45.46,36.08 45.65,36.27 RP3.16
CBG0: length 3
  TOP w0.14: J1.13 37.31,36.22 37.41,36.32 RP2.9
CBG1: length 3
  TOP w0.14: J1.14 37.81,36.17 37.99,36.35 RP2.10
CBG2: length 3
  TOP w0.14: RP2.11 38.49,36.22 38.31,36.04 J1.15
CBG3: length 3
  TOP w0.14: J1.16 38.81,35.99 38.99,36.17 RP2.12
CBG4: length 3
  TOP w0.14: RP2.13 39.49,36.06 39.31,35.88 J1.17
CBG5: length 3
  TOP w0.14: J1.18 39.81,35.82 39.99,36 RP2.14
CBG6: length 3
  TOP w0.14: RP2.15 40.49,35.94 40.31,35.76 J1.19
CBG7: length 3.1
  TOP w0.14: RP2.16 41.07,35.97 40.81,35.7 J1.20
CBR0: length 3.2
  TOP w0.14: RP1.9 32.71,36.18 33.09,35.8 33.09,35.63 33.31,35.41 J1.5
CBR1: length 3.2
  TOP w0.14: RP1.10 33.29,36.15 33.48,35.96 33.48,35.79 33.81,35.46 J1.6
CBR2: length 3.2
  TOP w0.14: RP1.11 33.79,36.21 33.88,36.13 33.88,35.96 34.31,35.52 J1.7
CBR3: length 3.2
  TOP w0.14: J1.8 34.81,35.58 34.29,36.1 RP1.12
CBR4: length 3.2
  TOP w0.14: RP1.13 34.79,36.23 35.31,35.71 J1.9
CBR5: length 3.2
  TOP w0.14: J1.10 35.81,35.77 35.29,36.28 RP1.14
CBR6: length 3.2
  TOP w0.14: RP1.15 35.79,36.34 36.31,35.82 J1.11
CBR7: length 3.2
  TOP w0.14: RP1.16 36.37,36.35 36.81,35.91 J1.12
CCLK: length 3.3
  TOP w0.14: RP4.9 46.68,36.29 45.98,35.58 45.98,35.28 45.81,35.11 J1.30
CDEN: length 4.4
  TOP w0.14: RP4.13 48.76,36.39 48.96,36.19 49.09,36.19 49.36,35.92 49.36,35.51 49.1,35.26 48.36,35.26 47.81,34.7 J1.34
CHASSIS_ETH1: length 10.1
  TOP w0.635: 75.52,57.17 J6.SHLD1 ; J6.SHLD1 78.03,57.17 ; J6.SHLD1 76.78,58.42 ; J6.SHLD1 76.78,55.91 ; 91.01,57.17 J6.SHLD2 ; J6.SHLD2 93.53,57.17 ; J6.SHLD2 92.27,55.91 ; J6.SHLD2 92.27,58.42
CHASSIS_ETH2: length 10.1
  TOP w0.635: J7.SHLD2 71.56,57.17 ; J7.SHLD2 70.3,55.91 ; J7.SHLD2 69.04,57.17 ; J7.SHLD2 70.3,58.42 ; 53.55,57.17 J7.SHLD1 ; J7.SHLD1 54.81,58.42 ; J7.SHLD1 56.06,57.17 ; J7.SHLD1 54.81,55.91
CHASSIS_SD: length 3.4
  BOTTOM w0.381: J4.14 112.82,69.61 113.21,69.22 ; 95.82,69.09 96.34,69.61 J4.13
CHASSIS_USB0: length 7.8
  BOTTOM w0.508: J3.S3 v1(36.4,68.92) ; J3.S4 v1(47.58,68.92) ; J3.S1 v1(37.14,66.37) ; J3.S2 v1(46.82,66.37) ; FB13.2 v1(48.98,68.28)
CHASSIS_USB1: length 18.9
  TOP w0.635: 30.42,59.15 J5.S2 ; J5.S2 28.85,60.72 ; J5.S2 32,60.72 ; J5.S2 30.42,62.3
  LY6_SIG2 w0.635: 17.29,59.15 J5.S1 ; J5.S1 18.87,60.72 ; J5.S1 17.29,62.3 ; J5.S1 15.72,60.72 ; 30.42,59.15 J5.S2 ; J5.S2 32,60.72 ; J5.S2 28.85,60.72 ; J5.S2 30.42,62.3
CHSYNC: length 3.4
  TOP w0.14: J1.32 46.81,34.9 47.76,35.85 RP4.11
CLK_25M: length 3.6
  BOTTOM w0.14: R190.1 100.28,35.92 98.49,35.92 98.21,36.2 U23.25
CLK_25M_R: length 72.8
  TOP w0.14: R24.2 61.48,47.9 61.48,48.76 63.03,50.31 63.03,51.92 63.87,52.75 69.55,52.75 70.29,53.5 70.29,54.41 71.16,55.28 73.3,55.28 73.5,55.08 73.52,55.06 77.9,55.06 78.88,56.03 90.62,56.03 91.82,54.82 98.42,54.82 102.19,51.05 v1(104.14,51.05)
  LY3_SIG1 w0.127: v1(103.38,33.91) 102.95,33.47 102.38,33.47 101.74,34.11 101.74,36.77 102.88,37.92 102.88,48.09 104.14,49.35 v1(104.14,51.05)
  BOTTOM w0.14: R190.2 102.78,35.23 103.39,34.62 103.39,33.91 v1(103.38,33.91)
COM_BTRST: length 55.1
  TOP w0.14: U12.10 53.32,10.26 52.76,9.7 v1(52.76,9.34)
  LY6_SIG2 w0.127: v1(52.76,9.34) 52.76,9.33 50.91,7.48 50.54,7.48 50.13,7.89 42.86,7.89 42.3,8.45 37,8.45 32.48,12.97 31.01,12.97 30.75,13.23 30.75,17.63 21.72,26.66 21.1,26.66 20.13,27.63 20.13,27.87 19.87,28.13 16.7,28.13 16.62,28.04 16.25,28.04 15.98,28.31 14.24,28.31 v1(13.47,29.09)
  BOTTOM w0.14: A1.10 v1(13.47,29.09)
COM_BTUARTDEBUG: length 1.7
  BOTTOM w0.14: A1.32 24.95,23.09 TP12.1
COM_SLOW_CLK: length 46.6
  LY6_SIG2 w0.127: v1(25.48,34.37) 26.42,33.43 26.42,31.49 28.45,29.46 28.45,28.57 31.77,25.25 31.77,24.65 34.75,21.67 40.28,21.67 46.91,21.67 47.56,21.02 49.84,21.02 50.15,21.32 52.29,21.32 54.29,19.33 55.22,19.33 v1(56.01,18.54)
  BOTTOM w0.14: U29.10 55.57,18.97 v1(56.01,18.54) ; R188.2 22.69,36.78 23.32,37.41 24.7,37.41 25.24,36.87 25.24,36.44 25.23,36.42 25.23,34.62 v1(25.48,34.37)
COM_SLOW_CLK_XO: length 3.7
  TOP w0.14: Y2.7 22.69,36.14 22.69,36.78 22.82,36.91 23.45,36.91 23.7,36.65 v1(24.72,36.65)
  BOTTOM w0.14: R187.2 v1(24.72,36.65)
COM_WL_RS232_RX: length 23.3
  LY6_SIG2 w0.127: v1(13.31,26.09) 16.57,22.83 16.57,22.68 17.16,22.09 22.14,22.09 25.19,19.04 25.19,14.18 v1(26.04,13.34)
  BOTTOM w0.14: A1.7 v1(13.31,26.09) ; TP15.1 v1(26.04,13.34)
COM_WL_RS232_TX: length 28.4
  LY6_SIG2 w0.127: v1(13.33,27.09) 13.33,26.93 15.26,25 15.26,24.66 15.79,24.13 16.62,24.13 17.11,23.64 21.12,23.64 25.78,18.98 25.78,15.81 26.61,14.98 26.61,10.22 v1(26.04,9.65)
  BOTTOM w0.14: A1.8 v1(13.33,27.09) ; TP19.1 v1(26.04,9.65)
COM_WL_UART_DBG: length 23.9
  LY6_SIG2 w0.127: v1(13.42,24.21) 16.01,21.61 22.01,21.61 23.18,20.44 23.18,19.53 23.77,18.94 24.02,18.94 24.72,18.23 24.72,12.87 v1(26.04,11.56)
  BOTTOM w0.14: A1.5 13.54,24.09 v1(13.42,24.21) ; TP17.1 v1(26.04,11.56)
COMAUD_CLK: length 37.1
  LY6_SIG2 w0.127: v1(24.47,29.03) 25.6,29.03 28.53,26.11 28.53,25.56 29.36,24.73 29.36,24.02 32.85,20.52 35.74,20.52 37.39,18.88 43.6,18.88 44.13,18.35 51.5,18.35 52.29,19.14 52.98,19.14 v1(53.42,18.7)
  BOTTOM w0.14: A1.26 24.41,29.09 v1(24.47,29.03) ; U29.13 53.62,18.95 53.42,18.75 v1(53.42,18.7)
COMAUD_FSYNC: length 49.7
  TOP w0.14: v1(55.84,10.24) 55.84,9.73 55.72,9.61 U12.11
  LY6_SIG2 w0.127: v1(22.05,30.09) 22.57,29.57 22.57,27.05 33.83,15.79 33.83,15.1 34.89,14.05 35.57,14.05 35.82,13.8 42.38,13.8 42.99,14.41 44.45,14.41 47.38,11.47 47.38,11.37 49.78,8.97 51.08,8.97 52.21,10.09 52.21,10.62 52.59,11 55.07,11 v1(55.84,10.24)
  BOTTOM w0.14: A1.25 v1(22.05,30.09)
COMAUD_IN: length 39.9
  LY6_SIG2 w0.127: v1(24.31,32.82) 27.94,29.19 27.94,28.22 31.26,24.9 31.26,24.44 34.54,21.16 36.13,21.16 36.65,20.64 47.22,20.64 47.78,20.07 50.13,20.07 50.88,20.82 52.08,20.82 v1(54.27,18.62)
  BOTTOM w0.14: U29.12 v1(54.27,18.62) ; v1(24.31,32.82) 23.59,32.09 A1.23
COMAUD_OUT: length 50.7
  TOP w0.14: U12.12 55.7,8.96 v1(55.84,9.09)
  LY6_SIG2 w0.127: v1(22.03,31.09) 21.61,30.67 21.61,29.9 21.86,29.65 21.9,29.65 22.2,29.36 22.2,26.89 32.94,16.14 32.94,15.34 33.86,14.41 33.86,12.88 37.23,9.52 46.15,9.52 46.89,8.78 49.16,8.78 49.3,8.64 51.22,8.64 52.37,9.79 55.14,9.79 v1(55.84,9.09)
  BOTTOM w0.14: A1.24 v1(22.03,31.09)
COMBTUARTCTS: length 38.8
  TOP w0.14: U11.12 53.1,15.95 v1(53.11,15.93)
  LY6_SIG2 w0.127: v1(24.59,26.87) 25.11,26.35 25.84,26.35 26.1,26.09 26.1,24.65 35.6,15.16 47.21,15.16 47.95,14.41 51.6,14.41 v1(53.11,15.93)
  BOTTOM w0.14: v1(24.59,26.87) 24.38,27.09 A1.28
COMBTUARTRTS: length 34.2
  TOP w0.14: U11.10 49.57,17.25 v1(48.83,16.51)
  LY6_SIG2 w0.127: v1(48.83,16.51) 45.6,16.51 45.56,16.55 44.44,16.55 43.95,16.07 36.59,16.07 35.43,17.22 33.99,17.22 26.94,24.28 26.94,25.71 25.98,26.68 25.55,26.68 24.59,27.64 v1(24.59,27.89)
  BOTTOM w0.14: A1.27 24.39,28.09 v1(24.59,27.89)
COMBTUARTRX: length 53.6
  TOP w0.14: U11.13 48.95,15.3 48.8,15.44 47.89,15.44 47.56,15.1 47.56,14.62 47.89,14.28 47.91,14.28 48.15,14.04 48.15,6.42 v1(48.27,6.29)
  LY6_SIG2 w0.127: v1(21.09,24.54) 21.09,24.25 26.44,18.9 26.44,16.65 27.06,16.02 28,16.02 28.71,15.31 28.71,11.38 33.8,6.29 48.27,6.29 v1(48.27,6.29)
  BOTTOM w0.14: v1(21.09,24.54) 21.64,25.09 A1.30
COMBTUARTTX: length 40.8
  TOP w0.14: U11.11 52.7,16.6 52.78,16.52 v1(53.34,16.52)
  LY6_SIG2 w0.127: v1(24.85,25.86) 24.85,25.44 35.46,14.83 45.89,14.83 47.35,13.37 49.52,13.37 50.23,14.08 51.84,14.08 52.87,15.11 53.59,15.11 53.85,15.37 53.85,16 53.34,16.51 53.35,16.51 v1(53.34,16.52)
  BOTTOM w0.14: A1.29 24.62,26.09 v1(24.85,25.86)
COMWL_IRQ: length 65.8
  TOP w0.14: v1(53.23,17.6) 53.86,16.96 53.86,13.45 56.53,10.78 56.53,8.71 56.13,8.31 U12.13
  LY6_SIG2 w0.127: v1(13.47,28.09) 12.96,28.6 12.96,29.3 14.19,30.53 17.58,30.53 17.78,30.73 17.78,31.58 18.03,31.84 22,31.84 23,30.84 23,29.78 24.26,28.52 24.85,28.52 26.43,26.95 26.94,26.44 27.45,25.93 27.45,25.04 27.71,24.78 28.59,24.78 28.85,24.52 28.85,23.81 34.55,18.11 36.33,18.11 37.67,16.78 38.5,16.78 39.57,17.84 39.94,17.84 40.44,17.34 46.93,17.34 47.37,17.78 51.66,17.78 51.99,17.45 52.36,17.45 52.52,17.6 v1(53.23,17.6)
  BOTTOM w0.14: A1.9 v1(13.47,28.09)
CRFILT: length 2.3
  BOTTOM w0.14: U16.9 44.82,53.48 45.34,52.96 C195.1
CVSYNC: length 3.4
  TOP w0.14: RP4.12 48.26,35.71 47.31,34.76 J1.33
DDR_A0: length 44
  TOP w0.14: RP5.7 82.71,12.21 82.55,12.37 82.33,12.37 82.2,12.24 82.2,11.66 82.11,11.57 81.91,11.57 81.79,11.68 81.79,11.79 81.64,11.94 81.41,11.94 81.18,11.71 80.93,11.71 80.8,11.84 80.8,12.27 80.65,12.42 80.04,12.42 79.91,12.29 79.91,11.71 79.79,11.58 79.23,11.58 79.1,11.71 79.1,12.27 78.95,12.42 78.59,12.42 78.17,11.99 v2(77.91,11.99)
  LY6_SIG2 w0.127: v2(76.74,27.41) 76.35,27.81 76.35,28.36 76.1,28.61 75.78,28.61 75.52,28.86 75.52,29.72 75.34,29.9 74.94,29.9 74.75,29.71 74.75,29.17 75.53,28.38 75.53,27.26 76.1,26.69 76.1,26.24 75.76,25.9 75.02,25.9 74.81,25.69 74.81,25.24 74.96,25.09 75.09,25.09 75.24,24.94 75.24,24.73 75.09,24.58 74.96,24.58 74.81,24.44 74.81,24.08 75.01,23.88 75.98,23.88 76.21,23.65 76.21,21.79 75.47,21.06 75.47,19.09 76.04,18.52 76.46,18.52 76.61,18.37 76.61,17.87 76.5,17.76 76.5,17.46 76.89,17.07 76.89,16.48 77.03,16.35 77.33,16.35 77.5,16.18 77.5,15.99 77.27,15.76 77.27,15.28 77.17,15.18 77.17,13.41 77.51,13.07 77.51,11.74 76.71,10.94 76.71,8.85 76.87,8.69 77.1,8.69 77.23,8.82 77.23,10.75 77.43,10.95 77.76,10.95 77.91,11.11 v2(77.91,11.99)
  BOTTOM w0.14: U32.N3 v2(77.91,11.99) ; U26.F3 v2(76.74,27.41)
DDR_A1: length 42.9
  TOP w0.14: v2(78.75,9.6) 78.31,10.03 77.45,10.03 77.27,9.86 77.27,9.58 77.65,9.19 77.75,9.19 78.11,9.19 78.44,8.86 78.77,8.86 78.85,8.94 80.5,8.94 80.98,8.46 RP6.5
  LY6_SIG2 w0.127: v2(74.89,22.61) 73.89,21.62 73.89,18.45 74.94,17.4 74.94,16.17 75.3,15.81 75.3,15.72 75.3,15.46 75.91,14.85 75.91,10.55 75.11,9.75 75.11,9.43 74.78,9.11 74.78,6.91 75.16,6.53 75.16,6.07 75.39,5.84 75.64,5.84 75.79,5.99 75.79,6.66 75.94,6.81 76.15,6.81 76.29,6.66 76.29,5.99 76.44,5.84 76.65,5.84 76.8,5.99 76.8,6.61 76.95,6.76 77.16,6.76 77.31,6.61 77.31,5.99 77.5,5.81 78.48,5.81 78.8,6.12 78.8,6.43 78.49,6.73 77.82,6.73 77.52,7.03 77.52,7.36 78.75,8.58 v2(78.75,9.6)
  BOTTOM w0.14: U32.P7 78.34,9.2 v2(78.75,9.6) ; U26.H1 74.74,25.88 74.89,25.73 v2(74.89,22.61)
DDR_A2: length 45.7
  LY6_SIG2 w0.127: v2(77.54,28.21) 77.54,28.33 77.15,28.72 77.15,30.76 77.06,30.85 76.9,31.01 75.74,31.01 75.5,31.26 75.5,31.6 75.72,31.82 76.9,31.82 77.15,31.58 77.15,31.24 77.62,30.77 77.62,28.71 77.93,28.4 77.93,27.01 78.28,26.66 78.28,25.1 77.92,24.73 77.92,22.8 78.61,22.11 80.48,22.11 80.73,21.86 80.73,19.13 80.47,18.87 80.47,18.68 80.61,18.54 81.35,18.54 81.58,18.31 81.58,18.12 81.87,17.83 81.87,14.73 82.02,14.58 82.48,14.58 82.61,14.45 82.61,14.19 82.49,14.07 82.02,14.07 81.87,13.92 81.87,13.31 80.8,12.25 80.8,11.89 80.5,11.58 79.08,11.58 v2(78.7,11.96)
  BOTTOM w0.14: RP7.5 84.51,11.07 84.44,11 77.3,11 77.15,11.15 77.15,11.4 77.32,11.58 78.32,11.58 v2(78.7,11.96) 78.8,11.91 U32.P3 ; v2(77.54,28.21) U26.E4
DDR_A3: length 42.7
  TOP w0.14: RP5.4 81.03,13.71 80.65,13.34 80.14,13.34 79.99,13.49 79.99,14.48 79.89,14.58 79.69,14.58 79.51,14.4 79.51,14.17 79.25,13.92 79.03,13.92 78.75,14.2 78.47,14.2 78.35,14.08 78.15,14.08 77.88,14.35 77.7,14.35 77.55,14.2 77.55,13.96 v2(77.91,13.6)
  LY6_SIG2 w0.127: v2(77.91,13.6) 77.62,13.6 77.5,13.72 77.5,13.97 77.63,14.1 78.16,14.1 78.31,13.94 78.31,13.07 78.04,12.79 78.04,12.5 78.29,12.24 78.29,12.24 78.31,12.22 78.31,11.28 78.67,10.92 80.2,10.92 83.27,13.99 83.27,15.09 83.13,15.22 82.55,15.22 82.38,15.39 82.38,15.57 82.54,15.73 83.12,15.73 83.27,15.88 83.27,16.09 83.12,16.24 82.53,16.24 82.38,16.39 82.38,16.6 82.53,16.75 83.12,16.75 83.26,16.89 83.26,17.14 82.94,17.47 82.94,18.03 82.52,18.45 82.19,18.45 81.24,19.41 81.24,22.36 80.97,22.63 78.86,22.63 78.31,23.18 78.31,24.53 78.53,24.75 78.76,24.75 79.23,24.28 79.44,24.28 79.61,24.46 79.61,24.99 79.07,25.53 79.07,25.9 78.59,26.37 78.59,26.64 78.88,26.92 78.88,27.12 78.58,27.41 v2(78.34,27.41)
  BOTTOM w0.14: U32.N2 v2(77.91,13.6) ; U26.C3 v2(78.34,27.41)
DDR_A4: length 43.2
  TOP w0.14: RP6.7 82.65,7.46 82.48,7.29 82.48,6.5 82.33,6.35 82.12,6.35 81.97,6.5 81.97,6.81 81.82,6.96 81.54,6.96 81.41,6.83 81.41,6.07 81.24,5.89 81.06,5.89 80.88,6.07 80.88,7.11 80.52,7.47 80.19,7.47 79.94,7.72 79.94,8.15 79.7,8.39 79.33,8.39 78.93,7.99 v2(78.71,7.99)
  LY6_SIG2 w0.127: v2(79.14,26.61) 79.14,26.3 79.36,26.09 79.53,26.09 79.68,26.23 79.68,27.29 79.83,27.44 80.04,27.44 80.19,27.29 80.19,26.45 80.34,26.3 81.14,26.3 81.5,25.94 81.5,25.87 84.49,22.88 84.49,22.23 84.71,22.01 84.89,22.01 85.05,22.16 85.21,22.16 85.45,21.92 85.45,19.76 85.07,19.38 85.07,19 85.45,18.62 85.45,13.3 81.57,9.42 81.57,8.94 82,8.52 82,8.23 81.41,7.65 81.03,7.65 80.85,7.82 80.85,8.15 80.51,8.5 79.46,8.5 79.12,8.16 79.12,7.32 78.87,7.06 78.62,7.06 78.46,7.23 78.46,7.74 v2(78.71,7.99)
  BOTTOM w0.14: U32.P8 v2(78.71,7.99) ; U26.C2 v2(79.14,26.61)
DDR_A5: length 42
  TOP w0.14: v2(78.71,13.6) 78.5,13.6 78.1,13.2 77.74,13.2 77.07,13.87 77.07,14.3 77.43,14.66 78.67,14.66 79.05,15.04 79.99,15.04 80.82,14.21 83.13,14.21 RP5.3
  LY3_SIG1 w0.127: v2(78.71,13.6) 79.05,13.93 79.24,13.93 79.61,14.3 80.52,14.3 80.7,14.48 80.7,14.65 80.51,14.84 79.42,14.84 79.15,15.11 79.15,15.34 79.35,15.54 80.31,15.54 80.49,15.71 80.49,15.92 80.29,16.12 79.2,16.12 79.07,16.25 79.07,16.46 79.25,16.63 80.24,16.63 80.39,16.78 80.39,16.99 80.24,17.14 78.85,17.14 78.68,17.3 78.68,17.51 78.82,17.65 80.15,17.65 80.32,17.82 80.32,18.03 80.2,18.16 79.5,18.16 79.35,18.3 79.35,18.51 79.5,18.66 80.22,18.66 80.4,18.84 80.4,19.05 80.28,19.17 79.51,19.17 79.36,19.33 79.36,19.66 79.51,19.81 80.12,19.81 80.3,19.99 80.3,22.02 79.64,22.68 79.64,23.75 80.12,24.23 80.12,24.5 79.69,24.92 78.41,24.92 78.26,25.07 78.26,26.29 78.98,27.01 79.33,27.01 79.53,26.8 79.53,26.39 79.69,26.23 79.87,26.23 80.09,26.45 80.23,26.45 80.35,26.32 80.35,26.01 79.96,25.62 v2(79.54,25.62)
  BOTTOM w0.14: U32.P2 v2(78.71,13.6) ; U26.B1 v2(79.54,25.62)
DDR_A6: length 43
  TOP w0.14: v2(79.51,7.99) 78.92,7.41 78.92,6.65 78.52,6.25 78.52,5.56 78.67,5.41 80.8,5.41 81.49,5.41 81.49,5.41 82,5.41 83.13,6.54 RP6.8
  LY6_SIG2 w0.127: v2(78.34,29.01) 79.76,29.01 81.54,27.23 81.58,27.23 86.48,22.33 86.48,11.25 81.03,5.81 79.8,5.81 79.53,6.07 79.53,6.53 79.91,6.91 79.91,7.59 v2(79.51,7.99)
  BOTTOM w0.14: v2(78.34,29.01) 77.94,29.41 U26.D5 ; U32.R8 v2(79.51,7.99)
DDR_A7: length 45.4
  LY6_SIG2 w0.127: v2(79.51,13.6) 79.79,13.32 79.79,13.16 79.64,13 78.92,13 78.76,12.85 78.76,12.59 78.94,12.41 79.68,12.41 80.24,12.98 80.24,13.19 80.56,13.51 80.57,13.51 80.8,13.74 80.8,14.21 80.64,14.38 79.74,14.38 79.56,14.55 79.56,14.78 79.71,14.93 80.67,14.93 80.79,15.05 80.79,15.3 80.65,15.44 79.3,15.44 79.13,15.61 79.13,15.82 79.3,15.99 80.06,15.99 80.21,16.14 80.21,16.35 80.06,16.5 79.48,16.5 79.33,16.65 79.33,16.84 79.5,17.01 80.53,17.01 80.67,17.15 80.67,17.36 80.53,17.5 79.79,17.5 79.66,17.63 79.66,17.85 79.21,18.3 78.92,18.3 78.71,18.5 78.71,19.4 78.86,19.55 79.31,19.55 79.46,19.7 79.46,19.95 79.29,20.12 77.85,20.12 77.69,20.28 77.69,20.49 77.82,20.63 79.56,20.63 79.71,20.77 79.71,21.03 79.48,21.26 77.55,21.26 77.14,21.67 77.14,25.66 76.59,26.21 76.59,26.49 76.84,26.75 77.07,26.75 77.6,26.21 77.6,25.82 v2(77.56,25.77)
  BOTTOM w0.14: U32.R2 v2(79.51,13.6) 79.51,13 79.71,12.8 80.37,12.8 80.87,13.3 80.87,14.69 81.16,14.99 83.83,14.99 84.13,14.68 84.13,12.83 84.31,12.65 RP7.8 ; v2(77.56,25.77) 77.53,25.77 77.53,26.62 U26.E2
DDR_A8: length 45.9
  LY6_SIG2 w0.127: v2(80.37,8) 80.37,7.55 80.73,7.19 80.73,6.76 80.91,6.58 81.08,6.58 82.84,8.33 82.84,8.63 82.29,9.18 82.29,9.39 82.44,9.54 82.65,9.54 83.15,9.04 83.36,9.04 83.51,9.19 83.51,9.4 83.01,9.9 83.01,10.11 83.16,10.26 83.37,10.26 83.95,9.68 84.13,9.68 84.28,9.83 84.28,10.06 83.73,10.62 83.73,10.83 83.88,10.97 84.09,10.97 84.31,10.75 84.52,10.75 85.17,11.4 85.17,12.26 85.97,13.06 85.97,22.12 80.27,27.82 78.73,27.82 v2(78.34,28.21)
  BOTTOM w0.14: v2(78.34,28.21) U26.D4 ; v2(80.37,8) U32.T8 79.91,8.69 80.22,8.99 80.58,8.99 81.13,8.43 81.13,8.05 80.78,7.7 80.78,7.04 81.01,6.81 81.44,6.81 81.64,7.01 81.64,7.82 81.87,8.05 82.15,8.05 82.3,7.9 82.3,7.49 82.48,7.32 82.84,7.32 83.76,8.24 83.76,8.98 84.35,9.57 RP7.2
DDR_A9: length 42.7
  LY3_SIG1 w0.127: v2(79.51,11.99) 79.51,11.74 79.31,11.53 77.7,11.53 77.52,11.72 77.52,12.21 77.74,12.43 77.97,12.43 78.12,12.58 78.12,13.01 78.27,13.16 78.48,13.16 78.63,13.01 78.63,12.58 78.78,12.43 78.99,12.43 79.14,12.58 79.14,13.01 79.28,13.16 79.49,13.16 79.64,13.01 79.64,12.58 79.79,12.43 80.53,12.43 80.73,12.64 80.73,12.95 80.53,13.16 80.53,13.36 80.68,13.51 80.89,13.51 81.09,13.31 81.31,13.31 81.74,13.75 81.74,13.88 81.59,14.04 81.28,14.04 81.11,14.21 81.11,14.42 81.23,14.55 81.61,14.55 81.76,14.69 81.76,14.93 81.61,15.07 81.08,15.07 80.93,15.22 80.93,15.43 81.08,15.58 81.61,15.58 81.73,15.71 81.73,16.07 81.56,16.24 81.34,16.24 81.16,16.42 81.16,16.63 81.28,16.75 81.61,16.75 81.76,16.9 81.76,17.16 81.61,17.31 81.03,17.31 80.85,17.48 80.85,17.69 80.98,17.81 81.61,17.81 81.76,17.96 81.76,18.19 81.46,18.48 81.46,18.67 81.76,18.96 81.76,19.2 81.56,19.4 81.35,19.4 81.16,19.21 81,19.21 80.85,19.36 80.85,19.62 81.08,19.85 81.08,20.09 80.83,20.34 80.83,22.21 80.19,22.85 80.19,23.77 80.52,24.1 80.52,24.64 79.94,25.22 79.35,25.22 79.12,25.45 79.12,25.96 78.97,26.12 78.78,26.12 78.63,25.96 78.63,25.54 v2(78.68,25.49)
  BOTTOM w0.14: U26.C1 78.74,25.56 v2(78.68,25.49) ; RP7.6 84.4,11.57 84.26,11.43 83.19,11.43 83.03,11.59 83.03,12.79 82.87,12.95 82.64,12.95 82.47,12.79 82.47,11.67 82.31,11.51 82.08,11.51 81.91,11.67 81.91,12.38 81.8,12.5 81.57,12.5 81.35,12.28 81.35,11.78 81.11,11.53 79.69,11.53 79.51,11.7 v2(79.51,11.99) U32.R3
DDR_A10: length 42.3
  TOP w0.14: RP6.3 82.26,9.46 81.34,10.39 76.13,10.39 75.95,10.21 75.95,9.96 v2(76.31,9.6)
  LY3_SIG1 w0.127: v2(76.31,9.6) 76.71,9.19 78.26,9.19 78.37,9.09 81.35,9.09 85.05,12.78 85.05,24.08 83.39,25.73 83.07,25.73 79.38,29.42 77.94,29.42 v2(76.74,28.21)
  BOTTOM w0.14: U32.L7 v2(76.31,9.6) ; v2(76.74,28.21) U26.F4
DDR_A11: length 45.8
  LY6_SIG2 w0.127: v2(79.56,9.64) 79.36,9.44 79.36,9.19 79.66,8.89 80.75,8.89 81.06,9.2 81.06,9.63 84.79,13.36 84.79,18.54 83.99,19.35 83.99,19.78 84.13,19.93 84.69,19.93 84.84,20.08 84.84,20.29 84.69,20.44 84.13,20.44 83.99,20.59 83.99,20.8 84.13,20.95 84.69,20.95 84.84,21.1 84.84,21.31 84.69,21.46 84.16,21.46 83.99,21.63 83.99,22.67 83.77,22.89 83.57,23.09 81.57,25.08 81.25,25.08 80.48,25.86 80.19,25.86 79.99,25.65 79.99,24.85 80.11,24.73 80.46,24.73 80.7,24.48 80.7,24.3 80.49,24.09 79.86,24.09 v2(79.24,23.47)
  BOTTOM w0.102: v2(79.24,23.47) 77.83,23.47 76.73,24.57 76.73,26.62 U26.F2
  BOTTOM w0.14: RP7.4 77.71,10.57 77.52,10.39 77.52,10.19 77.7,10.01 79.19,10.01 v2(79.56,9.64) U32.R7
DDR_A12: length 41.3
  TOP w0.14: v2(77.88,9.6) 78.09,9.6 78.49,9.19 78.92,9.19 79.15,9.42 79.15,9.91 79.31,10.06 79.76,10.06 79.97,9.86 79.97,9.32 80.09,9.19 80.68,9.19 80.8,9.32 80.8,9.83 80.93,9.95 81.16,9.95 81.31,9.8 81.31,9.04 81.47,8.89 81.69,8.89 82,9.19 82.15,9.19 82.38,8.96 RP6.4
  LY3_SIG1 w0.127: v2(77.54,27.41) 77.77,27.41 78.17,27.81 79.3,27.81 79.53,27.58 79.53,27.31 79.76,27.08 80.04,27.08 80.22,27.25 80.45,27.25 81.03,26.67 81.03,26.31 80.7,25.98 80.7,25.98 80.7,25.63 81.11,25.22 81.33,25.22 81.72,25.6 81.98,25.6 83.53,24.05 83.53,21.99 83.39,21.84 82.98,21.84 82.84,21.69 82.84,21.48 82.98,21.33 83.39,21.33 83.53,21.18 83.53,19.28 83.98,18.83 83.98,13.24 80.96,10.21 76.77,10.21 76.61,10.06 76.61,9.91 76.92,9.6 v2(77.88,9.6)
  BOTTOM w0.14: U26.E3 v2(77.54,27.41) ; v2(77.88,9.6) 77.51,9.23 U32.N7
DDR_A13: length 45.7
  LY6_SIG2 w0.127: v2(75.14,27.41) 74.73,27.82 74.73,28.38 74.5,28.61 74.17,28.61 73.47,29.31 73.47,31.64 73.64,31.82 74.89,31.82 75.06,31.65 75.06,31.19 74.89,31.02 74.16,31.02 73.95,30.81 73.95,30.45 74.18,30.22 76.09,30.22 76.33,29.98 76.33,28.85 76.58,28.61 76.9,28.61 77.15,28.36 77.15,27.15 77.98,26.31 77.98,25.33 77.53,24.88 77.53,22.1 77.91,21.71 79.84,21.71 80.22,21.34 80.22,19.58 79.61,18.97 79.61,18.62 80.19,18.04 80.95,18.04 81.3,17.68 81.3,13.49 80.35,12.54 v2(80.35,11.99)
  BOTTOM w0.14: U32.T3 v2(80.35,11.99) 80.35,12.03 81.39,13.07 81.39,14.27 81.57,14.45 82.1,14.45 82.23,14.31 82.23,13.65 82.4,13.49 82.63,13.49 82.79,13.65 82.79,14.26 82.98,14.45 83.34,14.45 83.6,14.2 83.6,12.47 84,12.07 RP7.7 ; U26.H3 v2(75.14,27.41)
DDR_A14: length 42.1
  LY3_SIG1 w0.127: v2(80.38,9.6) 81.12,9.6 84.49,12.96 84.49,19.1 84.08,19.51 84.08,22.45 84.54,22.91 84.54,23.87 83.67,24.74 83.36,24.74 82.84,25.26 82.84,25.46 79.17,29.13 78.87,29.13 78.73,28.99 78.73,28.82 78.54,28.62 78.13,28.62 77.93,28.42 77.93,28.05 77.7,27.82 77.3,27.82 77.13,27.65 77.13,27.09 76.97,26.92 76.46,26.92 76.33,27.05 76.33,27.63 76.16,27.81 76.1,27.81 75.55,27.81 v2(75.14,28.21)
  BOTTOM w0.14: v2(75.14,28.21) U26.H4 ; U32.T7 79.98,9.2 v2(80.38,9.6) 80.38,9.89 80.52,10.03 81.24,10.03 81.4,9.87 81.4,8.93 81.57,8.76 81.77,8.76 81.95,8.95 81.95,9.82 82.14,10.01 82.37,10.01 82.51,9.87 82.51,8.52 82.68,8.36 82.91,8.36 83.07,8.52 83.07,9.86 83.28,10.07 RP7.3
DDR_BA0: length 42.9
  TOP w0.14: v2(77.1,12.83) 76.84,12.83 76.64,13.03 76.64,13.26 76.84,13.46 77.07,13.46 77.81,12.73 78.06,12.73 78.34,13 78.72,13 79,13.28 79.23,13.28 79.51,13 80.91,13 81.21,13.31 81.41,13.31 81.74,12.98 81.92,12.98 82.15,13.21 RP5.5
  LY6_SIG2 w0.102: 78.18,28.62 78.2,28.59 78.5,28.59 78.88,28.21 v2(79.18,28.21)
  LY6_SIG2 w0.127: v2(77.1,12.83) 76.77,13.16 76.77,15.82 75.96,16.63 75.96,17.88 74.96,18.88 74.96,21.29 75.75,22.07 75.75,23.13 75.39,23.49 74.75,23.49 74.43,23.82 74.43,25.9 74.71,26.19 75.34,26.19 75.55,26.39 75.55,26.83 75.35,27.02 74.54,27.02 74.37,27.19 74.37,27.59 73.93,28.03 73.93,28.03 73.93,28.39 73.13,29.19 73.13,31.39 73.13,32.16 73.6,32.62 76.89,32.62 77.94,31.57 77.94,28.85 78.18,28.62
  BOTTOM w0.14: v2(77.1,12.83) 77.07,12.83 77.07,12.84 U32.M2 ; U26.C4 78.74,28.61 v2(79.18,28.21)
DDR_BA1: length 42.9
  TOP w0.14: RP6.6 82.57,7.96 82.1,7.49 81.85,7.49 81.74,7.59 81.74,7.87 81.59,8.03 80.91,8.03 80.24,8.69 79.06,8.69 78.88,8.51 78.59,8.51 78.44,8.36 77.4,8.36 77.02,8.74 77.02,8.92 77.15,9.04 77.37,9.04 77.62,8.8 v2(77.86,8.8)
  LY6_SIG2 w0.127: v2(78.74,24.19) 78.74,23.3 78.96,23.08 79.79,23.08 79.94,23.23 79.94,23.52 80.08,23.66 80.69,23.66 80.95,23.93 81.35,23.93 81.79,23.48 81.79,22.66 81.92,22.53 82.75,22.53 82.96,22.32 82.96,22.09 82.81,21.94 81.91,21.94 81.76,21.79 81.76,21.58 81.91,21.43 82.81,21.43 82.96,21.28 82.96,21.07 82.81,20.92 81.91,20.92 81.76,20.78 81.76,20.57 81.91,20.42 82.81,20.42 82.97,20.26 82.97,20.02 82.81,19.86 82.12,19.86 81.97,19.71 81.97,19.46 82.18,19.25 82.48,19.25 83.78,17.96 83.78,13.78 83.7,13.71 80.72,10.73 80.55,10.56 77.82,10.56 77.48,10.21 77.48,9.18 v2(77.86,8.8)
  BOTTOM w0.14: U32.N8 77.51,8.45 v2(77.86,8.8) ; U26.E1 77.14,24.8 77.75,24.19 v2(78.74,24.19)
